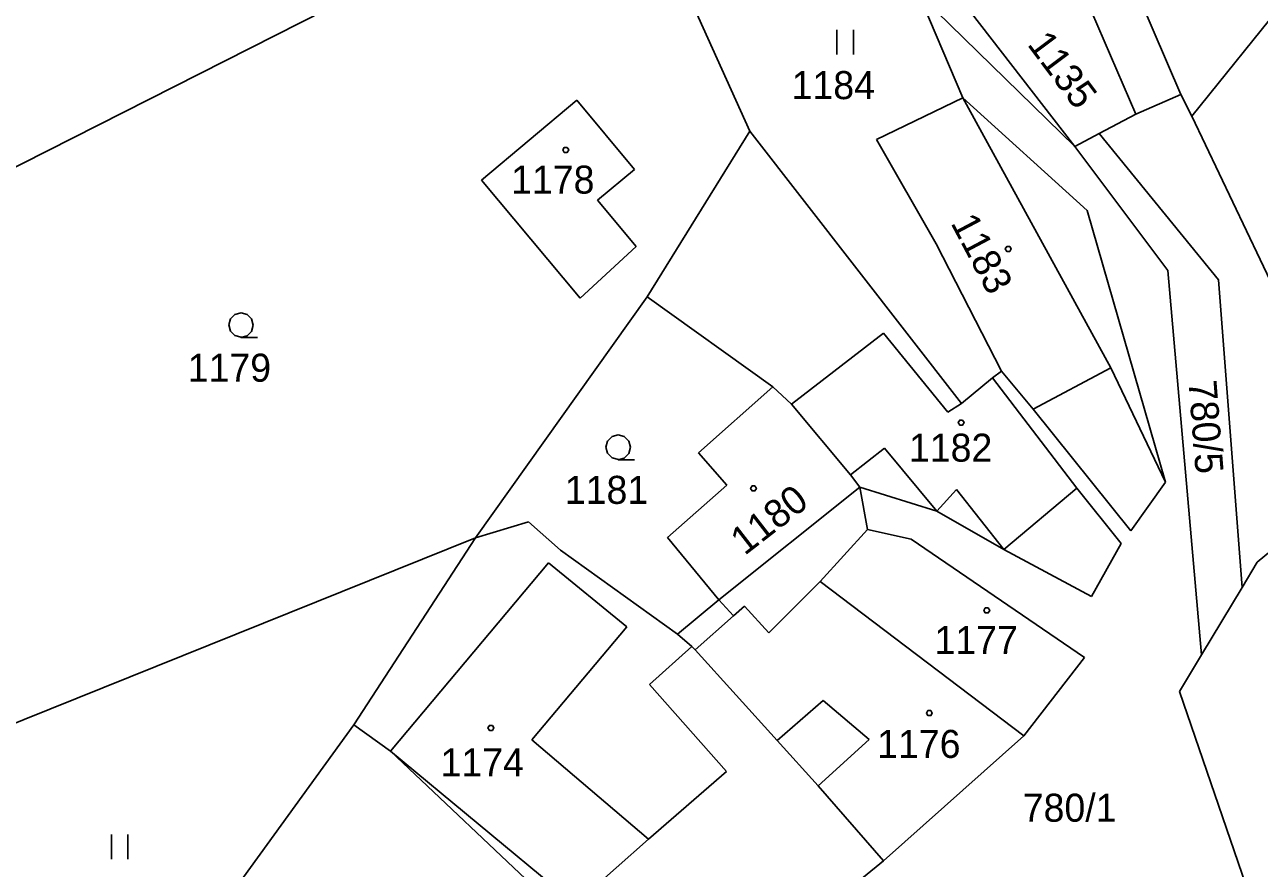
# Model space of a CAD drawing. Extents: x -609861 to -605046, y -1120287 to -1116307.
# Drawn here: x -607474 to -607399.1, y -1118987.9 to -1118936.8 of the extents above; entities that cross this region are included whole.
import ezdxf

# ---------------------------------------------------------------- set-up
doc = ezdxf.new("R2010")
doc.units = 0
for name, color, linetype in [('Vrstva 1', 7, 'Continuous'), ('Vrstva 2', 7, 'Continuous'), ('Vrstva 3', 7, 'Continuous'), ('Vrstva 4', 7, 'Continuous'), ('Vrstva 5', 7, 'Continuous')]:
    doc.layers.add(name, color=color, linetype=linetype)

msp = doc.modelspace()

# ---------------------------------------------------------------- linework, layer by layer
at = {"layer": 'Vrstva 1'}
for p, q in [((-607413.63, -1118918.14), (-607403.84, -1118940.98)), ((-607437.49, -1118926.61), (-607485.99, -1118951.18)), ((-607437.49, -1118926.61), (-607430, -1118943.21)), ((-607406.57, -1118942.19), (-607411.09, -1118931.7)), ((-607403.17, -1118942.31), (-607394.57, -1118931.57)), ((-607417.63, -1118934.64), (-607410.27, -1118944.15)), ((-607417.06, -1118941.19), (-607419.5, -1118935.48)), ((-607418.69, -1118935.94), (-607410.27, -1118944.15)), ((-607406.57, -1118942.19), (-607403.84, -1118940.98)), ((-607403.84, -1118940.98), (-607403.17, -1118942.31)), ((-607446.28, -1118946.18), (-607440.48, -1118941.33)), ((-607440.48, -1118941.33), (-607436.99, -1118945.53)), ((-607422.3, -1118943.72), (-607417.06, -1118941.19)), ((-607409.53, -1118948.02), (-607417.06, -1118941.19)), ((-607408.79, -1118943.36), (-607406.57, -1118942.19)), ((-607403.17, -1118942.31), (-607396.39, -1118956.56)), ((-607430, -1118943.21), (-607436.23, -1118953.27)), ((-607430, -1118943.21), (-607417.14, -1118959.73)), ((-607418.68, -1118950.05), (-607422.3, -1118943.72)), ((-607410.27, -1118944.15), (-607408.79, -1118943.36)), ((-607408.79, -1118943.36), (-607401.56, -1118952.23)), ((-607410.27, -1118944.15), (-607404.63, -1118951.67)), ((-607440.28, -1118953.35), (-607446.28, -1118946.18)), ((-607436.99, -1118945.53), (-607439.23, -1118947.4)), ((-607439.23, -1118947.4), (-607436.88, -1118950.2)), ((-607404.78, -1118964.5), (-607409.53, -1118948.02)), ((-607436.88, -1118950.2), (-607440.28, -1118953.35)), ((-607414.72, -1118957.78), (-607418.68, -1118950.05)), ((-607404.63, -1118951.67), (-607402.59, -1118974.98)), ((-607401.56, -1118952.23), (-607400.12, -1118970.89)), ((-607436.23, -1118953.27), (-607446.64, -1118967.87)), ((-607436.23, -1118953.27), (-607428.59, -1118958.73)), ((-607417.14, -1118959.73), (-607415.26, -1118958.18)), ((-607415.26, -1118958.18), (-607414.72, -1118957.78)), ((-607410.15, -1118964.87), (-607415.26, -1118958.18)), ((-607414.72, -1118957.78), (-607412.81, -1118960.07)), ((-607433.11, -1118962.73), (-607428.59, -1118958.73)), ((-607428.59, -1118958.73), (-607427.46, -1118959.78)), ((-607427.46, -1118959.78), (-607423.88, -1118964.05)), ((-607412.81, -1118960.07), (-607406.88, -1118967.46)), ((-607431.38, -1118964.69), (-607433.11, -1118962.73)), ((-607423.88, -1118964.05), (-607423.32, -1118964.81)), ((-607434.98, -1118967.85), (-607431.38, -1118964.69)), ((-607422.86, -1118967.37), (-607423.32, -1118964.81)), ((-607423.32, -1118964.81), (-607418.65, -1118966.26)), ((-607407.46, -1118968.23), (-607410.15, -1118964.87)), ((-607406.88, -1118967.46), (-607404.78, -1118964.5)), ((-607399.2, -1118969.36), (-607394.84, -1118965.74)), ((-607418.65, -1118966.26), (-607414.58, -1118968.58)), ((-607446.64, -1118967.87), (-607443.42, -1118966.9)), ((-607443.42, -1118966.9), (-607441.48, -1118968.62)), ((-607477.9, -1118980.46), (-607446.64, -1118967.87)), ((-607454.01, -1118979.23), (-607446.64, -1118967.87)), ((-607431.88, -1118971.65), (-607434.98, -1118967.85)), ((-607425.73, -1118970.53), (-607422.86, -1118967.37)), ((-607420.2, -1118967.97), (-607422.86, -1118967.37)), ((-607409.69, -1118975.14), (-607420.2, -1118967.97)), ((-607441.48, -1118968.62), (-607434.38, -1118973.72)), ((-607414.58, -1118968.58), (-607409.27, -1118971.43)), ((-607409.27, -1118971.43), (-607407.46, -1118968.23)), ((-607400.12, -1118970.89), (-607399.2, -1118969.36)), ((-607428.84, -1118973.64), (-607425.73, -1118970.53)), ((-607425.73, -1118970.53), (-607413.36, -1118979.89)), ((-607402.59, -1118974.98), (-607400.12, -1118970.89)), ((-607434.38, -1118973.72), (-607431.88, -1118971.65)), ((-607431.88, -1118971.65), (-607430.98, -1118972.61)), ((-607430.98, -1118972.61), (-607430.31, -1118972.02)), ((-607430.31, -1118972.02), (-607428.84, -1118973.64)), ((-607434.38, -1118973.72), (-607433.52, -1118974.47)), ((-607433.52, -1118974.47), (-607433.31, -1118974.67)), ((-607433.31, -1118974.67), (-607428.34, -1118980.17)), ((-607413.36, -1118979.89), (-607409.69, -1118975.14)), ((-607403.93, -1118977.2), (-607402.59, -1118974.98)), ((-607398.65, -1118992.57), (-607403.93, -1118977.2)), ((-607473.54, -1119006.1), (-607454.01, -1118979.23)), ((-607454.01, -1118979.23), (-607451.79, -1118980.82)), ((-607421.89, -1118987.47), (-607413.36, -1118979.89)), ((-607428.34, -1118980.17), (-607425.84, -1118982.92)), ((-607451.79, -1118980.82), (-607434.16, -1118997.46)), ((-607425.84, -1118982.92), (-607421.89, -1118987.47)), ((-607434.16, -1118997.46), (-607421.89, -1118987.47))]:
    msp.add_line(p, q, dxfattribs=at)
at = {"layer": 'Vrstva 3'}
for p, q in [((-607424.71, -1118937.07), (-607424.71, -1118938.57)), ((-607423.71, -1118938.57), (-607423.71, -1118937.07)), ((-607468.73, -1118985.88), (-607468.73, -1118987.38)), ((-607467.73, -1118987.38), (-607467.73, -1118985.88))]:
    msp.add_line(p, q, dxfattribs=at)
for points in [[(-607460.85, -1118955.71), (-607461.23, -1118955.61), (-607461.5, -1118955.34), (-607461.6, -1118954.97), (-607461.5, -1118954.6), (-607461.23, -1118954.33), (-607460.86, -1118954.23), (-607460.49, -1118954.33), (-607460.22, -1118954.6), (-607460.12, -1118954.98), (-607460.22, -1118955.36), (-607460.49, -1118955.63), (-607460.87, -1118955.73), (-607459.87, -1118955.73)], [(-607437.97, -1118963.12), (-607438.35, -1118963.02), (-607438.62, -1118962.75), (-607438.72, -1118962.38), (-607438.62, -1118962.01), (-607438.35, -1118961.74), (-607437.98, -1118961.64), (-607437.61, -1118961.74), (-607437.34, -1118962.01), (-607437.24, -1118962.39), (-607437.34, -1118962.77), (-607437.61, -1118963.04), (-607437.99, -1118963.14), (-607436.99, -1118963.14)]]:
    msp.add_lwpolyline(points, dxfattribs=at)
at = {"layer": 'Vrstva 4'}
for p, q in [((-607417.06, -1118941.19), (-607408.09, -1118957.56)), ((-607427.46, -1118959.78), (-607421.89, -1118955.47)), ((-607421.89, -1118955.47), (-607417.97, -1118960.26)), ((-607408.09, -1118957.56), (-607412.81, -1118960.07)), ((-607408.09, -1118957.56), (-607404.78, -1118964.5)), ((-607417.97, -1118960.26), (-607417.14, -1118959.73)), ((-607421.82, -1118962.45), (-607423.88, -1118964.05)), ((-607418.65, -1118966.26), (-607421.82, -1118962.45)), ((-607423.32, -1118964.81), (-607431.88, -1118971.65)), ((-607417.45, -1118964.94), (-607418.65, -1118966.26)), ((-607414.58, -1118968.58), (-607417.45, -1118964.94)), ((-607410.15, -1118964.87), (-607414.58, -1118968.58)), ((-607451.79, -1118980.82), (-607442.21, -1118969.39)), ((-607442.21, -1118969.39), (-607437.46, -1118973.28)), ((-607430.98, -1118972.61), (-607433.31, -1118974.67)), ((-607437.46, -1118973.28), (-607443.22, -1118980.13)), ((-607436.08, -1118976.78), (-607433.52, -1118974.47)), ((-607431.41, -1118982.05), (-607436.08, -1118976.78)), ((-607428.34, -1118980.17), (-607425.54, -1118977.74)), ((-607425.54, -1118977.74), (-607422.76, -1118980.12)), ((-607443.22, -1118980.13), (-607436.15, -1118986.16)), ((-607422.76, -1118980.12), (-607425.84, -1118982.92)), ((-607440.6, -1118990.09), (-607451.79, -1118980.82)), ((-607436.15, -1118986.16), (-607431.41, -1118982.05)), ((-607436.15, -1118986.16), (-607440.6, -1118990.09))]:
    msp.add_line(p, q, dxfattribs=at)
at = {"layer": 'Vrstva 5'}
for points in [[(-607441.07, -1118944.2), (-607440.98, -1118944.35), (-607441.07, -1118944.5), (-607441.25, -1118944.5), (-607441.34, -1118944.35), (-607441.25, -1118944.2)], [(-607414.22, -1118950.21), (-607414.13, -1118950.36), (-607414.22, -1118950.51), (-607414.4, -1118950.51), (-607414.49, -1118950.36), (-607414.4, -1118950.21)], [(-607417.08, -1118960.74), (-607416.99, -1118960.89), (-607417.08, -1118961.04), (-607417.26, -1118961.04), (-607417.35, -1118960.89), (-607417.26, -1118960.74)], [(-607429.68, -1118964.73), (-607429.59, -1118964.88), (-607429.68, -1118965.03), (-607429.86, -1118965.03), (-607429.95, -1118964.88), (-607429.86, -1118964.73)], [(-607415.53, -1118972.13), (-607415.44, -1118972.28), (-607415.53, -1118972.43), (-607415.71, -1118972.43), (-607415.8, -1118972.28), (-607415.71, -1118972.13)], [(-607419.01, -1118978.36), (-607418.92, -1118978.51), (-607419.01, -1118978.66), (-607419.19, -1118978.66), (-607419.28, -1118978.51), (-607419.19, -1118978.36)], [(-607445.61, -1118979.26), (-607445.52, -1118979.41), (-607445.61, -1118979.56), (-607445.79, -1118979.56), (-607445.88, -1118979.41), (-607445.79, -1118979.26)]]:
    msp.add_lwpolyline(points, close=True, dxfattribs=at)

# ---------------------------------------------------------------- texts
at = {"layer": 'Vrstva 2'}
for s, rotation, p in [('1135', 306.87619, (-607413.204, -1118937.954)), ('1183', 297.88076, (-607417.836, -1118948.777)), ('780/5', 274.50408, (-607403.381, -1118958.377)), ('1180', 37.81521, (-607430.31, -1118968.989))]:
    msp.add_text(s, height=1.7, rotation=rotation, dxfattribs=at).set_placement(p)
for s, p in [('1184', (-607427.457, -1118941.27)), ('1178', (-607444.477, -1118947)), ('1179', (-607464.097, -1118958.41)), ('1182', (-607420.337, -1118963.26)), ('1181', (-607441.217, -1118965.82)), ('1177', (-607418.787, -1118974.93)), ('1176', (-607422.267, -1118981.23)), ('1174', (-607448.757, -1118982.35)), ('780/1', (-607413.433, -1118985.1))]:
    msp.add_text(s, height=1.7, dxfattribs=at).set_placement(p)

doc.saveas('drawing.dxf')
